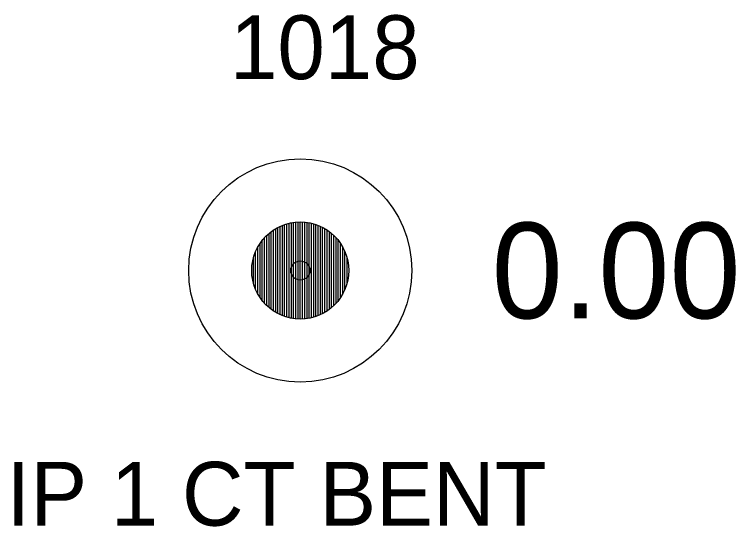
# Model space of a CAD drawing. Extents: x 1655137 to 1657928, y 1003994 to 1005407.
# Drawn here: x 1655883.91 to 1655895.22, y 1004389.69 to 1004397.71 of the extents above; entities that cross this region are included whole.
import ezdxf

# ---------------------------------------------------------------- set-up
doc = ezdxf.new("R2010")
doc.units = 0
for name, color, linetype in [('RD_EX_DV_Prop_txCode', 7, 'Continuous'), ('RD_EX_DV_PropPin', 7, 'Continuous'), ('RD_EX_TX_DV_Prop_ELEV', 7, 'Continuous'), ('RD_SMD_Locator', 7, 'Continuous')]:
    doc.layers.add(name, color=color, linetype=linetype)

msp = doc.modelspace()

# ---------------------------------------------------------------- linework, layer by layer
at = {"layer": 'RD_EX_DV_PropPin'}
for p, q in [((1655888.292, 1004392.946), (1655888.292, 1004394.454)), ((1655888.327, 1004392.942), (1655888.327, 1004394.458)), ((1655888.362, 1004392.94), (1655888.362, 1004394.46)), ((1655888.397, 1004392.939), (1655888.397, 1004394.461)), ((1655888.432, 1004392.94), (1655888.432, 1004394.46)), ((1655888.468, 1004392.942), (1655888.468, 1004394.458)), ((1655888.503, 1004392.946), (1655888.503, 1004394.454)), ((1655888.012, 1004393.043), (1655888.012, 1004394.356)), ((1655888.047, 1004393.024), (1655888.047, 1004394.375)), ((1655888.082, 1004393.007), (1655888.082, 1004394.393)), ((1655888.117, 1004392.992), (1655888.117, 1004394.407)), ((1655888.152, 1004392.979), (1655888.152, 1004394.42)), ((1655888.187, 1004392.968), (1655888.187, 1004394.431)), ((1655888.222, 1004392.959), (1655888.222, 1004394.44)), ((1655888.257, 1004392.952), (1655888.257, 1004394.448)), ((1655888.538, 1004392.952), (1655888.538, 1004394.448)), ((1655888.573, 1004392.959), (1655888.573, 1004394.44)), ((1655888.608, 1004392.968), (1655888.608, 1004394.431)), ((1655888.643, 1004392.979), (1655888.643, 1004394.42)), ((1655888.678, 1004392.992), (1655888.678, 1004394.407)), ((1655888.713, 1004393.007), (1655888.713, 1004394.393)), ((1655888.748, 1004393.024), (1655888.748, 1004394.375)), ((1655888.783, 1004393.043), (1655888.783, 1004394.356)), ((1655887.872, 1004393.149), (1655887.872, 1004394.251)), ((1655887.907, 1004393.118), (1655887.907, 1004394.282)), ((1655887.942, 1004393.09), (1655887.942, 1004394.31)), ((1655887.977, 1004393.065), (1655887.977, 1004394.334)), ((1655888.818, 1004393.065), (1655888.818, 1004394.334)), ((1655888.853, 1004393.09), (1655888.853, 1004394.31)), ((1655888.888, 1004393.118), (1655888.888, 1004394.282)), ((1655888.923, 1004393.149), (1655888.923, 1004394.251)), ((1655887.767, 1004393.273), (1655887.767, 1004394.126)), ((1655887.802, 1004393.226), (1655887.802, 1004394.174)), ((1655887.837, 1004393.185), (1655887.837, 1004394.215)), ((1655888.958, 1004393.185), (1655888.958, 1004394.215)), ((1655888.993, 1004393.226), (1655888.993, 1004394.174)), ((1655889.028, 1004393.273), (1655889.028, 1004394.126)), ((1655887.732, 1004393.33), (1655887.732, 1004394.069)), ((1655889.063, 1004393.33), (1655889.063, 1004394.069)), ((1655887.662, 1004393.504), (1655887.662, 1004393.896)), ((1655887.697, 1004393.402), (1655887.697, 1004393.998)), ((1655889.098, 1004393.402), (1655889.098, 1004393.998)), ((1655889.133, 1004393.504), (1655889.133, 1004393.896))]:
    msp.add_line(p, q, dxfattribs=at)
for radius in [1.75, 0.761]:
    msp.add_circle((1655888.397, 1004393.7), radius, dxfattribs=at)
at = {"layer": 'RD_SMD_Locator'}
msp.add_circle((1655888.398, 1004393.7), 0.15, dxfattribs=at)

# ---------------------------------------------------------------- texts
at = {"layer": 'RD_EX_DV_Prop_txCode'}
for s, p in [('1018', (1655887.295, 1004396.7)), ('IP 1 CT BENT', (1655883.791, 1004389.7))]:
    msp.add_text(s, height=1, dxfattribs=at).set_placement(p)
at = {"layer": 'RD_EX_TX_DV_Prop_ELEV'}
msp.add_text('0.00', height=1.5, dxfattribs=at).set_placement((1655891.398, 1004392.95))

doc.saveas('drawing.dxf')
